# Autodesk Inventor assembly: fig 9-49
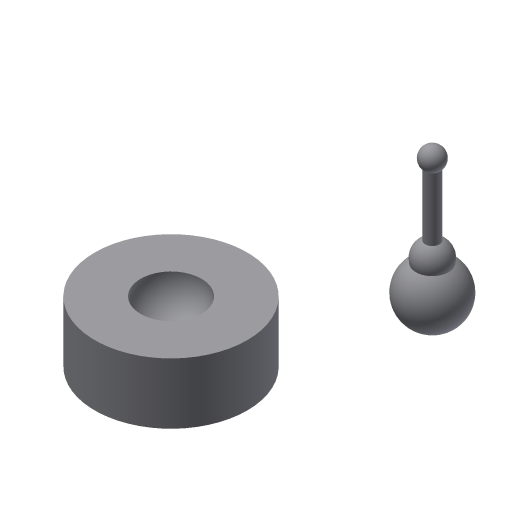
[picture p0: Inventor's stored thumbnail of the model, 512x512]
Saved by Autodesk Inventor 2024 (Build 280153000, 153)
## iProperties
Created: 2013-07
Part Number: fig 9-49
Document SubType Name: Assembly
Designer: CADCIM
Author: CADCIM
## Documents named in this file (3)
- D:\PROJECTS\Project 2023\RESOURCES INVENTOR 2024\RESOURCES INVENTOR 2024\Inventor_2023_Part\Inventor_2024_Part\c09_Inv_2024_prt\fig 9-50.iam
- D:\PROJECTS\Project 2023\RESOURCES INVENTOR 2024\RESOURCES INVENTOR 2024\Inventor_2023_Part\Inventor_2024_Part\c09_Inv_2024_prt\19.ipt
- D:\PROJECTS\Project 2023\RESOURCES INVENTOR 2024\RESOURCES INVENTOR 2024\Inventor_2023_Part\Inventor_2024_Part\c09_Inv_2024_prt\20.ipt
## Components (2 placed, 2 different names)
1. 19:1
2. 20:2
